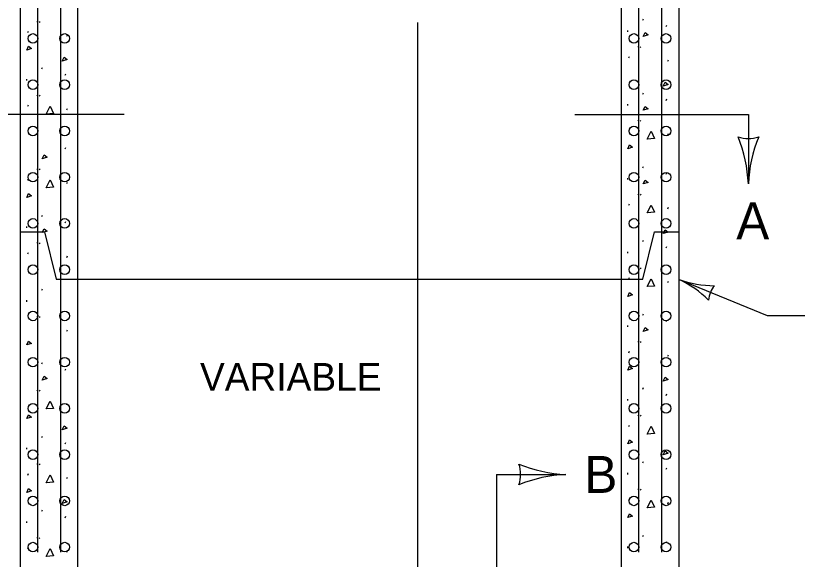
# Model space of a CAD drawing. Extents: x 49991.4 to 50028.3, y 49987.6 to 50011.4.
# Drawn here: x 50007.028 to 50008.719, y 49989.8 to 49990.975 of the extents above; entities that cross this region are included whole.
import ezdxf

# ---------------------------------------------------------------- set-up
doc = ezdxf.new("R2010")
doc.units = 0
for name, color, linetype in [('Level 1', 7, 'Continuous'), ('Level 2', 7, 'Continuous'), ('Level 3', 7, 'Continuous'), ('Level 6', 7, 'Continuous')]:
    doc.layers.add(name, color=color, linetype=linetype)

msp = doc.modelspace()

# ---------------------------------------------------------------- linework, layer by layer
at = {"layer": 'Level 1'}
for p, q in [((50007.0376, 49991.4777), (50007.0376, 49989.7777)), ((50008.4626, 49991.4777), (50008.4626, 49989.7777)), ((50007.0751, 49991.4401), (50007.0751, 49989.8151)), ((50007.1251, 49991.4401), (50007.1251, 49989.8151)), ((50008.3751, 49991.4401), (50008.3751, 49989.8151)), ((50008.4251, 49991.4401), (50008.4251, 49989.8151)), ((50007.0741, 49990.9635), (50007.0754, 49990.9615)), ((50007.0791, 49990.9627), (50007.0805, 49990.9607)), ((50008.3845, 49990.9653), (50008.3858, 49990.9683)), ((50008.4351, 49990.9516), (50008.4364, 49990.9546)), ((50007.0544, 49990.9388), (50007.0557, 49990.9418)), ((50008.351, 49990.9433), (50008.3513, 49990.9403)), ((50007.1388, 49990.9311), (50007.1401, 49990.9341)), ((50008.3737, 49990.9091), (50008.3751, 49990.9071)), ((50008.3788, 49990.9083), (50008.3801, 49990.9063)), ((50008.3541, 49990.8844), (50008.3554, 49990.8874)), ((50008.4384, 49990.8767), (50008.4398, 49990.8797)), ((50007.0848, 49990.8602), (50007.0861, 49990.8632)), ((50007.0513, 49990.8381), (50007.0517, 49990.8352)), ((50007.1355, 49990.8465), (50007.1368, 49990.8495)), ((50007.0741, 49990.804), (50007.0754, 49990.802)), ((50007.0791, 49990.8033), (50007.0805, 49990.8013)), ((50008.3845, 49990.8058), (50008.3858, 49990.8088)), ((50008.4351, 49990.7922), (50008.4364, 49990.7952)), ((50007.0544, 49990.7793), (50007.0557, 49990.7823)), ((50007.1388, 49990.7717), (50007.1401, 49990.7747)), ((50008.351, 49990.7838), (50008.3513, 49990.7808)), ((50008.3737, 49990.7497), (50008.3751, 49990.7477)), ((50008.3788, 49990.7489), (50008.3801, 49990.7469)), ((50008.3541, 49990.7249), (50008.3554, 49990.7279)), ((50008.4384, 49990.7173), (50008.4398, 49990.7203)), ((50007.1355, 49990.6871), (50007.1368, 49990.6901)), ((50007.0741, 49990.6445), (50007.0754, 49990.6425)), ((50007.0791, 49990.6438), (50007.0805, 49990.6418)), ((50008.3845, 49990.6464), (50008.3858, 49990.6494)), ((50008.4351, 49990.6327), (50008.4364, 49990.6357)), ((50007.0544, 49990.6199), (50007.0557, 49990.6229)), ((50008.351, 49990.6243), (50008.3513, 49990.6213)), ((50007.1388, 49990.6122), (50007.1401, 49990.6152)), ((50008.3737, 49990.5902), (50008.3751, 49990.5882)), ((50008.3788, 49990.5894), (50008.3801, 49990.5874)), ((50008.3541, 49990.5655), (50008.3554, 49990.5685)), ((50008.4384, 49990.5579), (50008.4398, 49990.5609)), ((50007.0848, 49990.5413), (50007.0861, 49990.5443)), ((50007.0513, 49990.5193), (50007.0517, 49990.5163)), ((50007.1355, 49990.5276), (50007.1368, 49990.5306)), ((50007.0376, 49990.5077), (50007.0905, 49990.5077)), ((50007.0905, 49990.5077), (50007.1158, 49990.4059)), ((50008.3844, 49990.4059), (50008.4097, 49990.5077)), ((50008.4097, 49990.5077), (50008.4626, 49990.5077)), ((50007.0741, 49990.4851), (50007.0754, 49990.4831)), ((50007.0791, 49990.4843), (50007.0805, 49990.4823)), ((50008.3845, 49990.4869), (50008.3858, 49990.4899)), ((50008.351, 49990.4649), (50008.3513, 49990.4619)), ((50008.4351, 49990.4733), (50008.4364, 49990.4763)), ((50007.0544, 49990.4604), (50007.0557, 49990.4634)), ((50007.1388, 49990.4527), (50007.1401, 49990.4557)), ((50008.3737, 49990.4307), (50008.3751, 49990.4287)), ((50008.3788, 49990.43), (50008.3801, 49990.428)), ((50007.1158, 49990.4059), (50008.3844, 49990.4059)), ((50008.3541, 49990.4061), (50008.3554, 49990.4091)), ((50008.4384, 49990.3984), (50008.4398, 49990.4014)), ((50007.0848, 49990.3818), (50007.0861, 49990.3848)), ((50007.0513, 49990.3598), (50007.0517, 49990.3568)), ((50008.3845, 49990.3275), (50008.3858, 49990.3305)), ((50007.0741, 49990.3256), (50007.0754, 49990.3236)), ((50007.0791, 49990.3249), (50007.0805, 49990.3229)), ((50008.4351, 49990.3138), (50008.4364, 49990.3168)), ((50007.1388, 49990.2933), (50007.1401, 49990.2963)), ((50008.351, 49990.3055), (50008.3513, 49990.3025)), ((50008.3737, 49990.2713), (50008.3751, 49990.2693)), ((50008.3788, 49990.2705), (50008.3801, 49990.2685)), ((50008.3541, 49990.2466), (50008.3554, 49990.2496)), ((50008.4384, 49990.2389), (50008.4398, 49990.2419)), ((50007.0848, 49990.2223), (50007.0861, 49990.2253)), ((50007.1355, 49990.2087), (50007.1368, 49990.2117)), ((50007.0741, 49990.1662), (50007.0754, 49990.1642)), ((50007.0791, 49990.1654), (50007.0805, 49990.1634)), ((50008.3845, 49990.168), (50008.3858, 49990.171)), ((50008.351, 49990.146), (50008.3513, 49990.143)), ((50008.4351, 49990.1543), (50008.4364, 49990.1573)), ((50007.1388, 49990.1338), (50007.1401, 49990.1368)), ((50008.3737, 49990.1118), (50008.3751, 49990.1098)), ((50008.3788, 49990.1111), (50008.3801, 49990.1091)), ((50008.3541, 49990.0871), (50008.3554, 49990.0901)), ((50007.0848, 49990.0629), (50007.0861, 49990.0659)), ((50007.1355, 49990.0493), (50007.1368, 49990.0523)), ((50007.0513, 49990.0409), (50007.0517, 49990.0379)), ((50008.3845, 49990.0085), (50008.3858, 49990.0115)), ((50007.0741, 49990.0067), (50007.0754, 49990.0047)), ((50007.0791, 49990.0059), (50007.0805, 49990.0039)), ((50008.4351, 49989.9949), (50008.4364, 49989.9979)), ((50007.0544, 49989.982), (50007.0557, 49989.985)), ((50007.1388, 49989.9744), (50007.1401, 49989.9774)), ((50008.351, 49989.9865), (50008.3513, 49989.9835)), ((50008.3737, 49989.9524), (50008.3751, 49989.9504)), ((50008.3788, 49989.9516), (50008.3801, 49989.9496)), ((50008.3541, 49989.9277), (50008.3554, 49989.9307)), ((50007.0848, 49989.9035), (50007.0861, 49989.9065)), ((50008.4384, 49989.92), (50008.4398, 49989.923)), ((50007.1355, 49989.8898), (50007.1368, 49989.8928)), ((50007.0513, 49989.8814), (50007.0517, 49989.8784)), ((50007.0741, 49989.8473), (50007.0754, 49989.8453)), ((50007.0791, 49989.8465), (50007.0805, 49989.8445)), ((50008.3845, 49989.8491), (50008.3858, 49989.8521)), ((50007.0544, 49989.8226), (50007.0557, 49989.8256)), ((50008.351, 49989.8271), (50008.3513, 49989.8241)), ((50008.4351, 49989.8355), (50008.4364, 49989.8385)), ((50007.1388, 49989.8149), (50007.1401, 49989.8179))]:
    msp.add_line(p, q, dxfattribs=at)
msp.add_lwpolyline([(50007.1626, 49991.4777), (50008.3376, 49991.4777), (50008.3376, 49989.4277), (50007.1626, 49989.4277)], close=True, dxfattribs=at)
for points in [[(50008.3851, 49990.9303), (50008.3891, 49990.9387), (50008.3958, 49990.9337), (50008.3851, 49990.9303)], [(50007.0521, 49990.9011), (50007.0561, 49990.9095), (50007.0627, 49990.9045), (50007.0521, 49990.9011)], [(50007.1289, 49990.8773), (50007.1329, 49990.8857), (50007.1395, 49990.8807), (50007.1289, 49990.8773)], [(50008.4285, 49990.823), (50008.4325, 49990.8313), (50008.4392, 49990.8263), (50008.4285, 49990.823)], [(50007.0938, 49990.7627), (50007.1028, 49990.7797), (50007.1098, 49990.764), (50007.0941, 49990.7627)], [(50008.3851, 49990.7709), (50008.3891, 49990.7792), (50008.3958, 49990.7742), (50008.3851, 49990.7709)], [(50008.3935, 49990.7083), (50008.4025, 49990.7253), (50008.4095, 49990.7097), (50008.3938, 49990.7083)], [(50008.3517, 49990.6873), (50008.3557, 49990.6957), (50008.3624, 49990.6907), (50008.3517, 49990.6873)], [(50007.0855, 49990.6657), (50007.0895, 49990.6741), (50007.0961, 49990.6691), (50007.0855, 49990.6657)], [(50007.0938, 49990.6032), (50007.1028, 49990.6202), (50007.1098, 49990.6045), (50007.0941, 49990.6032)], [(50008.3851, 49990.6114), (50008.3891, 49990.6197), (50008.3958, 49990.6147), (50008.3851, 49990.6114)], [(50007.0521, 49990.5822), (50007.0561, 49990.5905), (50007.0627, 49990.5855), (50007.0521, 49990.5822)], [(50008.3935, 49990.5489), (50008.4025, 49990.5659), (50008.4095, 49990.5502), (50008.3938, 49990.5489)], [(50007.0855, 49990.5063), (50007.0895, 49990.5146), (50007.0961, 49990.5096), (50007.0855, 49990.5063)], [(50008.4285, 49990.5041), (50008.4325, 49990.5124), (50008.4392, 49990.5074), (50008.4285, 49990.5041)], [(50008.3935, 49990.3894), (50008.4025, 49990.4064), (50008.4095, 49990.3907), (50008.3938, 49990.3894)], [(50008.3517, 49990.3684), (50008.3557, 49990.3767), (50008.3624, 49990.3717), (50008.3517, 49990.3684)], [(50008.3851, 49990.2925), (50008.3891, 49990.3008), (50008.3958, 49990.2958), (50008.3851, 49990.2925)], [(50007.0521, 49990.2633), (50007.0561, 49990.2717), (50007.0627, 49990.2667), (50007.0521, 49990.2633)], [(50008.3517, 49990.209), (50008.3557, 49990.2173), (50008.3624, 49990.2123), (50008.3517, 49990.209)], [(50007.0855, 49990.1874), (50007.0895, 49990.1957), (50007.0961, 49990.1907), (50007.0855, 49990.1874)], [(50008.4285, 49990.1851), (50008.4325, 49990.1935), (50008.4392, 49990.1885), (50008.4285, 49990.1851)], [(50007.0938, 49990.1249), (50007.1028, 49990.1418), (50007.1098, 49990.1262), (50007.0941, 49990.1249)], [(50007.0521, 49990.1039), (50007.0561, 49990.1122), (50007.0627, 49990.1072), (50007.0521, 49990.1039)], [(50007.1289, 49990.0801), (50007.1329, 49990.0884), (50007.1395, 49990.0834), (50007.1289, 49990.0801)], [(50008.3935, 49990.0705), (50008.4025, 49990.0875), (50008.4095, 49990.0718), (50008.3938, 49990.0705)], [(50008.3517, 49990.0495), (50008.3557, 49990.0578), (50008.3624, 49990.0529), (50008.3517, 49990.0495)], [(50008.4285, 49990.0257), (50008.4325, 49990.034), (50008.4392, 49990.029), (50008.4285, 49990.0257)], [(50007.0938, 49989.9654), (50007.1028, 49989.9824), (50007.1098, 49989.9667), (50007.0941, 49989.9654)], [(50007.0521, 49989.9444), (50007.0561, 49989.9527), (50007.0627, 49989.9477), (50007.0521, 49989.9444)], [(50007.1289, 49989.9206), (50007.1329, 49989.9289), (50007.1395, 49989.9239), (50007.1289, 49989.9206)], [(50008.3935, 49989.911), (50008.4025, 49989.928), (50008.4095, 49989.9124), (50008.3938, 49989.911)], [(50008.3517, 49989.8901), (50008.3557, 49989.8984), (50008.3624, 49989.8934), (50008.3517, 49989.8901)], [(50007.0938, 49989.8059), (50007.1028, 49989.8229), (50007.1098, 49989.8073), (50007.0941, 49989.8059)]]:
    msp.add_lwpolyline(points, dxfattribs=at)
for centre in [(50007.0655, 49990.9261), (50007.1342, 49990.9261), (50008.3651, 49990.9261), (50008.4347, 49990.9261), (50007.0655, 49990.8261), (50007.1342, 49990.8261), (50008.3651, 49990.8261), (50008.4347, 49990.8261), (50007.0655, 49990.7261), (50007.1342, 49990.7261), (50008.3651, 49990.7261), (50008.4347, 49990.7261), (50007.0655, 49990.6261), (50007.1342, 49990.6261), (50008.3651, 49990.6261), (50008.4347, 49990.6261), (50007.0655, 49990.5261), (50007.1342, 49990.5261), (50008.3651, 49990.5261), (50008.4347, 49990.5261), (50007.0655, 49990.4261), (50007.1342, 49990.4261), (50008.3651, 49990.4261), (50008.4347, 49990.4261), (50007.0655, 49990.3261), (50007.1342, 49990.3261), (50008.3651, 49990.3261), (50008.4347, 49990.3261), (50007.0655, 49990.2261), (50007.1342, 49990.2261), (50008.3651, 49990.2261), (50008.4347, 49990.2261), (50007.0655, 49990.1261), (50007.1342, 49990.1261), (50008.3651, 49990.1261), (50008.4347, 49990.1261), (50007.0655, 49990.0261), (50007.1342, 49990.0261), (50008.3651, 49990.0261), (50008.4347, 49990.0261), (50007.0655, 49989.9261), (50007.1342, 49989.9261), (50008.3651, 49989.9261), (50008.4347, 49989.9261), (50007.0655, 49989.8261), (50007.1342, 49989.8261), (50008.3651, 49989.8261), (50008.4347, 49989.8261)]:
    msp.add_circle(centre, 0.0104, dxfattribs=at)
at = {"layer": 'Level 3'}
for p, q in [((50007.8972, 49990.9607), (50007.8972, 49989.4277)), ((50008.654, 49990.3263), (50008.4626, 49990.4046)), ((50008.7452, 49990.3263), (50008.654, 49990.3263))]:
    msp.add_line(p, q, dxfattribs=at)
for centre, radius, start, end in [((50008.6126, 49990.7826), 0.073, 252.1388, 287.8612), ((50008.3023, 49990.5963), 0.3107, 2.8273, 22.0772), ((50008.6126, 49990.7826), 0.073, 252.1388, 287.8612), ((50008.3023, 49990.5963), 0.3107, 2.8273, 22.0772), ((50008.9088, 49990.5994), 0.2964, 157.456, 177.6395), ((50008.9088, 49990.5994), 0.2964, 157.456, 177.6395), ((50008.37, 49990.2025), 0.2223, 45.207, 65.3905), ((50008.5401, 49990.6244), 0.233, 250.5783, 269.8281), ((50008.5813, 49990.3561), 0.0548, 139.8898, 175.6122), ((50008.2302, 49990.2795), 0.2964, 247.456, 267.6395), ((50008.0471, 49989.9833), 0.073, 342.1388, 17.8612), ((50008.2333, 49989.673), 0.3107, 92.8273, 112.0772)]:
    msp.add_arc(centre, radius, start, end, dxfattribs=at)
at = {"layer": 'Level 6'}
for p, q in [((50007.2626, 49990.7617), (50006.8876, 49990.7617)), ((50008.2376, 49990.7617), (50008.6126, 49990.7617)), ((50008.6126, 49990.7617), (50008.6126, 49990.6117)), ((50008.068, 49989.9833), (50008.068, 49989.1527)), ((50008.068, 49989.9833), (50008.218, 49989.9833))]:
    msp.add_line(p, q, dxfattribs=at)

# ---------------------------------------------------------------- texts
at = {"layer": 'Level 2'}
for s, height, p in [('A', 0.0799, (50008.5865, 49990.4918)), ('VARIABLE', 0.06, (50007.4268, 49990.1642)), ('B', 0.0799, (50008.258, 49989.9433))]:
    msp.add_text(s, height=height, dxfattribs=at).set_placement(p)

doc.saveas('drawing.dxf')
